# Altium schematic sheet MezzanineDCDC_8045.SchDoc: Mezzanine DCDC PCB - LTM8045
size B; Date: 9/7/2021; Engineer: J. Juneau; DocumentNumber: 1006; Revision: 1.2; SheetNumber: 4; SheetTotal: 4
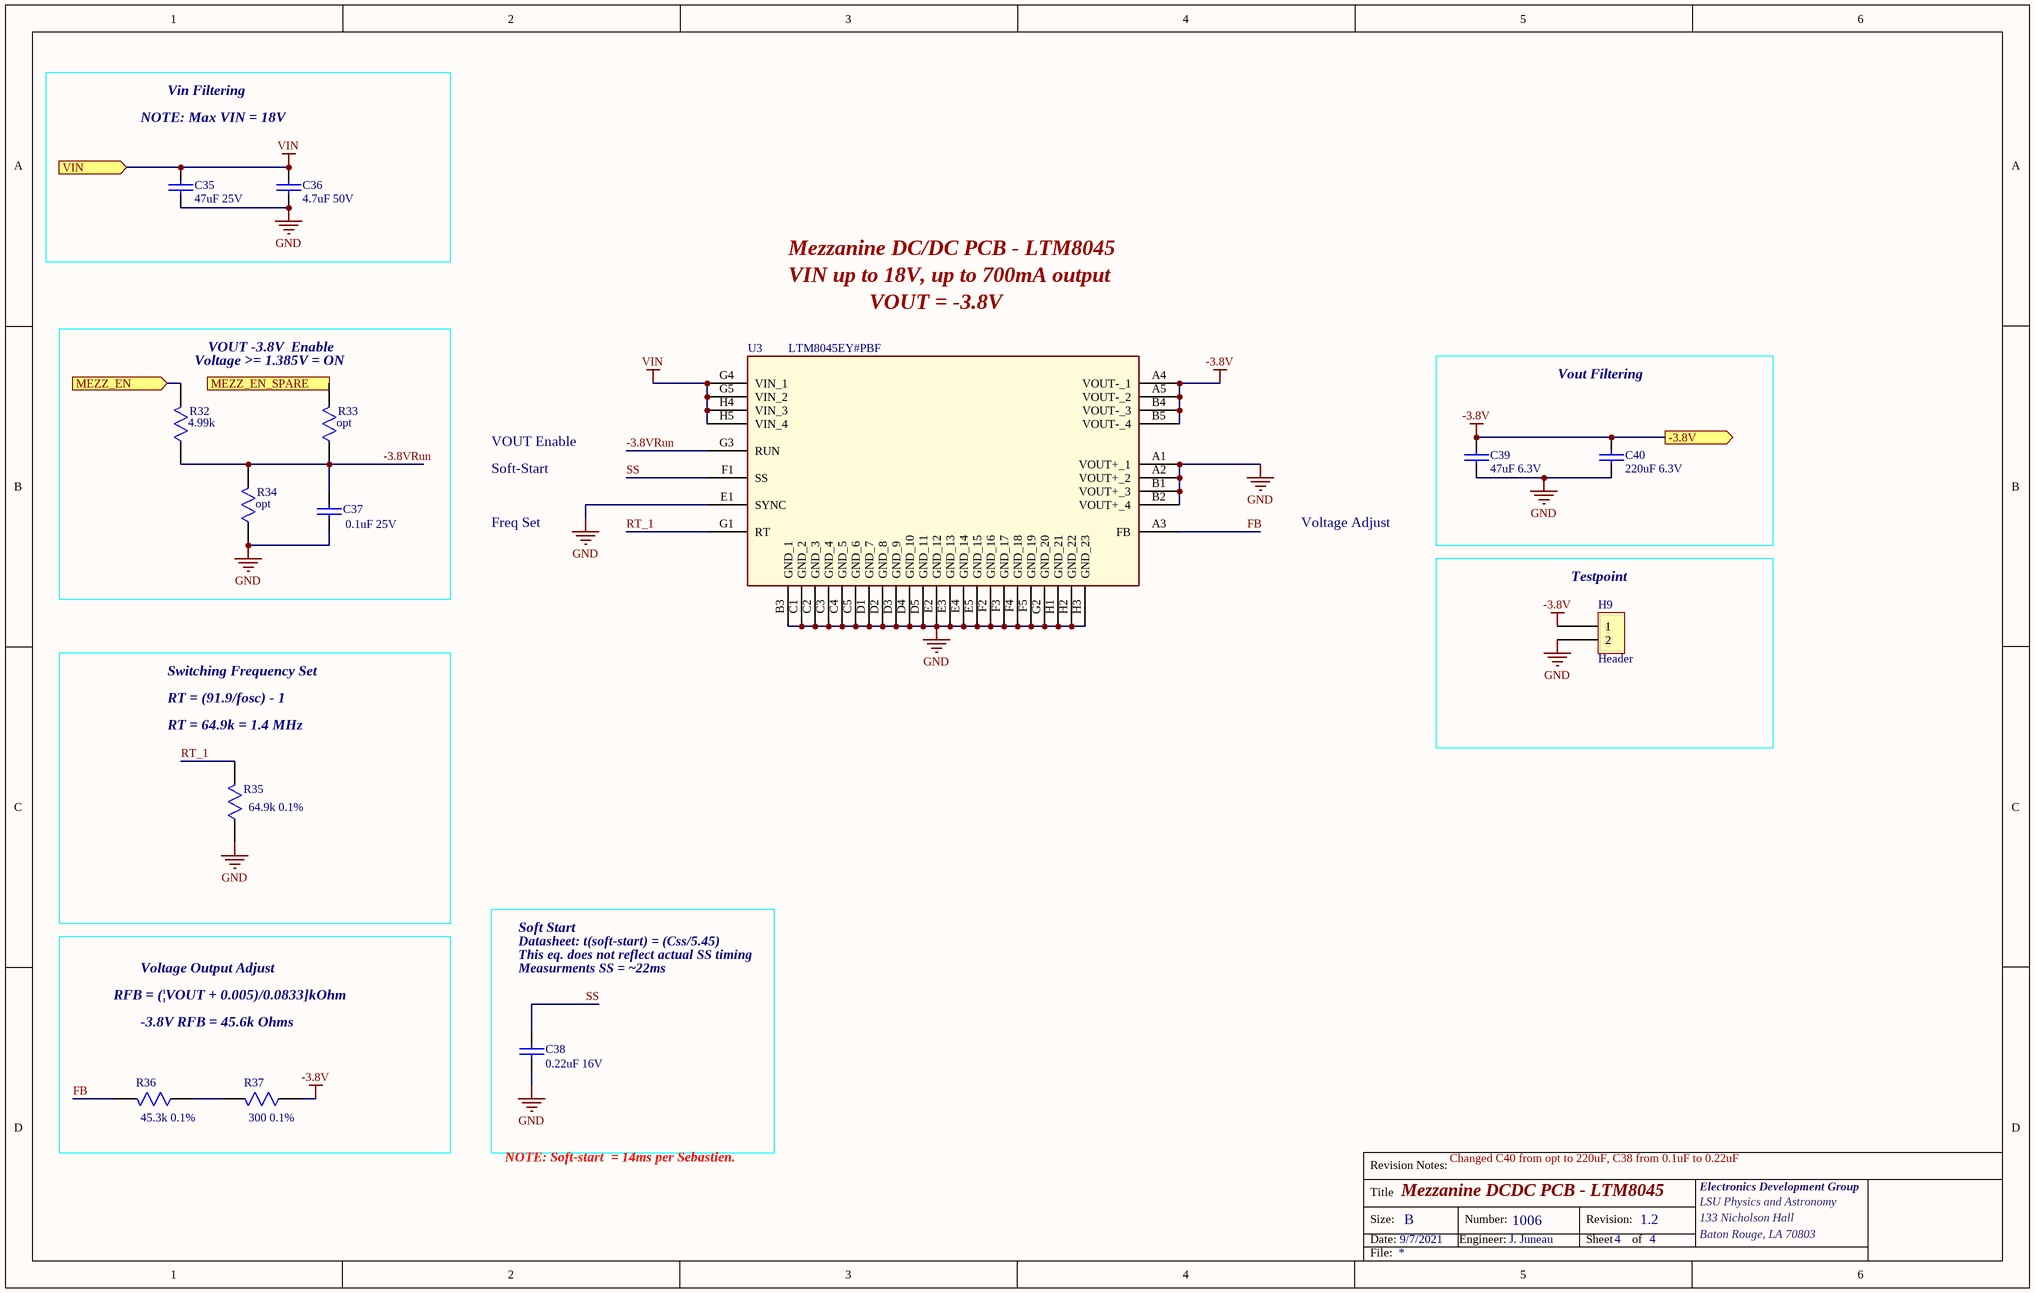
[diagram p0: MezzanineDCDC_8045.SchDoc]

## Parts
C35  value 47uF 25V  [CAP 1206 TDK]  (hidden comment: C3216X5R1E476M160AC)
C36  value 4.7uF 50V  [CAP 1206 TDK]  (hidden comment: UMK316BJ475KL-T)
C37  value 0.1uF 25V  [Cap 0603 TDK]  (hidden comment: C1608X7R1E104K080AA)
C38  value 0.22uF 16V  [Cap 0603 TDK]  (hidden comment: 0603YD224KAT2A)
C39  value 47uF 6.3V  [CAP 1206 TDK 2.3 Height]  (hidden comment: 12066D476MAT4A)
C40  value 220uF 6.3V  [CAP 1206 TDK 2.3 Height]  (hidden comment: GRM31CR60J227ME11L)
H9  Header  [Header 2Pin]
R32  value 4.99k  [Resistor ERJ2G/CRCW 0402]  (hidden comment: CRCW04024K99FKED)
R33  opt  [Resistor ERJ2G/CRCW 0402]
R34  opt  [Resistor ERJ2G/CRCW 0402]
R35  value 64.9k 0.1%  [Resistor 0603 - ERJ]  (hidden comment: ERJ-PB3B6492V)
R36  value 45.3k 0.1%  [Resistor 0603 - ERJ]  (hidden comment: ERA-3AEB4532V)
R37  value 300 0.1%  [Resistor 0603 - ERJ]  (hidden comment: ERA-3AEB301V)
U3  LTM8045EY#PBF  [LTM8045]

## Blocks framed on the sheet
Vout Filtering: C39 C40
Testpoint: H9
Soft Start: C38

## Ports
-3.8V (out), MEZZ_EN (in), MEZZ_EN_SPARE (in), VIN (in)

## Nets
-3.8V: C39.1 C40.1 H9.1 R37.1 U3.A4(VOUT-_1) U3.A5(VOUT-_2) U3.B4(VOUT-_3) U3.B5(VOUT-_4) ; port -3.8V
GND: C35.2 C36.2 C37.2 C38.2 C39.2 C40.2 H9.2 R34.1 R35.1 U3.A1(VOUT+_1) U3.A2(VOUT+_2) U3.B1(VOUT+_3) U3.B2(VOUT+_4) U3.B3(GND_1) U3.C1(GND_2) U3.C2(GND_3) U3.C3(GND_4) U3.C4(GND_5) U3.C5(GND_6) U3.D1(GND_7) U3.D2(GND_8) U3.D3(GND_9) U3.D4(GND_10) U3.D5(GND_11) U3.E1(SYNC) U3.E2(GND_12) U3.E3(GND_13) U3.E4(GND_14) U3.E5(GND_15) U3.F2(GND_16) U3.F3(GND_17) U3.F4(GND_18) U3.F5(GND_19) U3.G2(GND_20) U3.H1(GND_21) U3.H2(GND_22) U3.H3(GND_23)
VIN: C35.1 C36.1 U3.G4(VIN_1) U3.G5(VIN_2) U3.H4(VIN_3) U3.H5(VIN_4) ; port VIN
-3.8VRun: C37.1 R32.1 R33.1 R34.2 U3.G3(RUN)
FB: R36.2 U3.A3(FB)
MEZZ_EN: R32.2 ; port MEZZ_EN
MEZZ_EN_SPARE: R33.2 ; port MEZZ_EN_SPARE
RT_1: R35.2 U3.G1(RT)
SS: C38.1 U3.F1(SS)
NetR36_1: R36.1 R37.2

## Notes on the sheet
- Vin Filtering
- NOTE: Max VIN = 18V
- Mezzanine DC/DC PCB - LTM8045
- VIN up to 18V, up to 700mA output
- Voltage >= 1.385V = ON
- VOUT -3.8V  Enable
- VOUT = -3.8V
- VOUT Enable
- Soft-Start
- Freq Set
- Voltage Adjust
- Switching Frequency Set
- RT = (91.9/fosc) - 1
- (near R35) RT = 64.9k = 1.4 MHz
- Voltage Output Adjust
- Datasheet: t(soft-start) = (Css/5.45)
- This eq. does not reflect actual SS timing
- Measurments SS = |2ms
- RFB = (¦VOUT + 0.005)/0.0833]kOhm
- -3.8V RFB = 45.6k Ohms
- NOTE: Soft-start  = 14ms per Sebastien.
- Changed C40 from opt to 220uF, C38 from 0.1uF to 0.22uF

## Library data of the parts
C35 = Capacitor 1206: 47µF ±20% 25V Ceramic Capacitor X5R 1206 (3216 Metric)
C36 = Capacitor 1206: 4.7µF ±10% 50V Ceramic Capacitor X5R 1206 (3216 Metric)
C37 = Capacitor 0603 TDK: CAP CER 0.1UF 25V X7R 0603
C38 = Capacitor 0603 TDK: 0.22 µF ±10% 16V Ceramic Capacitor X5R 0603 (1608 Metric)
C39 = Capacitor 1206 2.3mmHeight: 47µF ±20% 6.3V Ceramic Capacitor X5R 1206 (3216 Metric)
C40 = Capacitor 1206 2.3mmHeight: 220 µF ±20% 6.3V Ceramic Capacitor X5R 1206 (3216 Metric)
H9 = Header - 2Pin: Connector Header Through Hole 2 position 0.100" (2.54mm)
R32 = ERJ2G Resistor 0402: RES, Thick Film, 4.99 kOhm, 1.0 %, 1/16 W, SMD, 0402
R33 R34 = ERJ2G Resistor 0402: Resistor 0402
R35 = Resistor 0603: 64.9 ±0.1% 0.2W, 1/5W Chip Resistor 0603 (1608 Metric) Automotive AEC-Q200, Pulse Withstanding Thick Film
R36 = Resistor 0603: RES SMD 45.3KOHM 0.1% 1/10W 0603
R37 = Resistor 0603: RES SMD 300 OHM 0.1% 1/10W 0603
U3 = LTM8045: Non-Isolated PoL Module DC DC Converter Output -2.5 ~ -15V, 2.5 ~ 15V - - 700mA 2.8V - 18V Input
